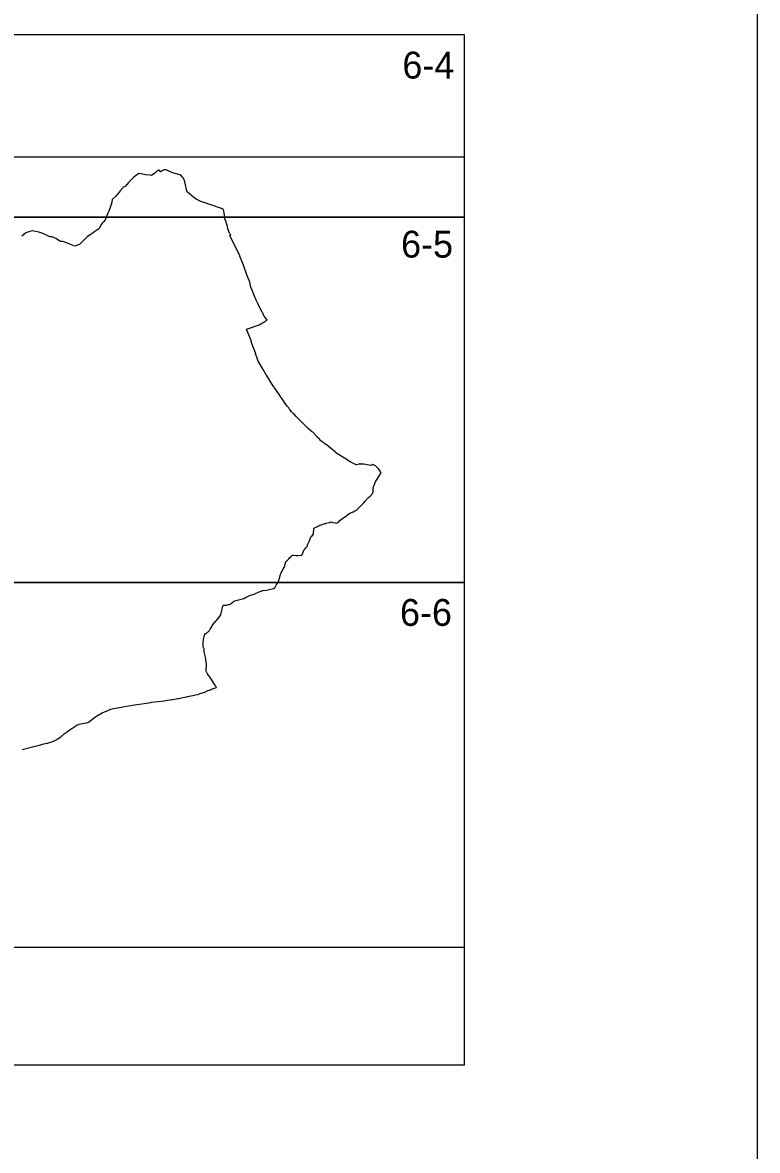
# Model space of a CAD drawing. Extents: x -447352 to -425530, y -1135906 to -1121091.
# Drawn here: x -444012.9 to -443761.4, y -1122276.2 to -1121890.1 of the extents above; entities that cross this region are included whole.
import ezdxf

# ---------------------------------------------------------------- set-up
doc = ezdxf.new("R2010")
doc.units = 0
for name, color, linetype in [('Vrstva 1', 7, 'Continuous'), ('Vrstva 10', 7, 'Continuous'), ('Vrstva 4', 7, 'Continuous')]:
    doc.layers.add(name, color=color, linetype=linetype)

msp = doc.modelspace()

# ---------------------------------------------------------------- linework, layer by layer
at = {"layer": 'Vrstva 1'}
msp.add_lwpolyline([(-445246.36, -1121535.97), (-445246.36, -1122585.97), (-443761.36, -1122585.97), (-443761.36, -1121535.97)], close=True, dxfattribs=at)
msp.add_lwpolyline([(-444013.07, -1122138.88), (-444009.53, -1122138.01), (-444006.76, -1122137.34), (-444006.09, -1122137.13), (-444004.6, -1122136.77), (-444004.39, -1122136.71), (-444002.96, -1122136.32), (-444002.36, -1122136.06), (-444002.14, -1122135.96), (-444001.98, -1122135.9), (-444001.16, -1122135.45), (-444001.1, -1122135.41), (-443999.79, -1122134.63), (-443998.64, -1122133.58), (-443997.99, -1122133.08), (-443997.86, -1122132.97), (-443997.84, -1122132.96), (-443997.68, -1122132.83), (-443997.53, -1122132.73), (-443996.73, -1122132.17), (-443996.67, -1122132.13), (-443996.6, -1122132.08), (-443996.09, -1122131.73), (-443995.72, -1122131.47), (-443995.06, -1122131.01), (-443994.47, -1122130.6), (-443994.31, -1122130.63), (-443994.3, -1122130.63), (-443994.28, -1122130.61), (-443993.55, -1122130.22), (-443990.59, -1122129.64), (-443990.17, -1122129.49), (-443988.14, -1122127.86), (-443987.67, -1122127.52), (-443987.64, -1122127.5), (-443987.28, -1122127.24), (-443987.1, -1122127.12), (-443985.71, -1122126.42), (-443984.3, -1122125.78), (-443984, -1122125.63), (-443982.74, -1122125.17), (-443981.74, -1122124.92), (-443976.03, -1122123.86), (-443974.61, -1122123.6), (-443972.9, -1122123.35), (-443969.03, -1122122.78), (-443968.79, -1122122.75), (-443964.49, -1122122.23), (-443963.96, -1122122.17), (-443961.81, -1122121.81), (-443961.49, -1122121.76), (-443959.83, -1122121.49), (-443959.43, -1122121.42), (-443958.02, -1122121.13), (-443956.73, -1122120.86), (-443956.52, -1122120.82), (-443955.35, -1122120.59), (-443954.68, -1122120.46), (-443954.66, -1122120.46), (-443953.75, -1122120.25), (-443953.68, -1122120.23), (-443953.03, -1122120.07), (-443952.68, -1122119.96), (-443951.79, -1122119.67), (-443951.35, -1122119.52), (-443950.7, -1122119.28), (-443950.58, -1122119.24), (-443949.49, -1122118.75), (-443949.49, -1122118.75), (-443949.37, -1122118.71), (-443948.72, -1122118.48), (-443948.63, -1122118.45), (-443948.2, -1122118.29), (-443946.54, -1122117.71), (-443946.56, -1122117.66), (-443946.67, -1122117.49), (-443946.83, -1122117.26), (-443947.05, -1122116.94), (-443948.75, -1122114.3), (-443948.96, -1122113.95), (-443949.13, -1122113.68), (-443949.57, -1122112.97), (-443950.1, -1122112.12), (-443949.94, -1122109.76), (-443949.93, -1122109.67), (-443950.32, -1122107.37), (-443950.32, -1122107.35), (-443950.33, -1122107.33), (-443950.33, -1122107.33), (-443950.33, -1122107.3), (-443950.74, -1122105.47), (-443950.75, -1122105.28), (-443950.81, -1122104.48), (-443950.91, -1122104.2), (-443950.92, -1122104.18), (-443951.03, -1122103.96), (-443951.07, -1122103.88), (-443951.08, -1122103.5), (-443951.11, -1122102.8), (-443951.06, -1122102.31), (-443951.06, -1122102.29), (-443950.97, -1122101.43), (-443950.95, -1122101.32), (-443950.66, -1122099.68), (-443950.58, -1122099.6), (-443950.28, -1122099.26), (-443950.22, -1122099.19), (-443949.96, -1122099.07), (-443949.9, -1122099.01), (-443949.64, -1122098.81), (-443949.41, -1122098.63), (-443949.2, -1122098.47), (-443949.14, -1122098.43), (-443949.06, -1122098.3), (-443948.98, -1122098.18), (-443948.87, -1122098.01), (-443948.65, -1122097.68), (-443948.23, -1122097.03), (-443948.1, -1122096.78), (-443948.09, -1122096.77), (-443947.95, -1122096.48), (-443947.9, -1122096.39), (-443947.72, -1122096.06), (-443947.58, -1122095.91), (-443947.28, -1122095.6), (-443947.11, -1122095.42), (-443946.83, -1122095.07), (-443946.7, -1122094.9), (-443946.01, -1122094.05), (-443945.35, -1122093.24), (-443945.06, -1122092.88), (-443944.82, -1122091.71), (-443944.76, -1122091.48), (-443944.69, -1122091.2), (-443944.37, -1122089.89), (-443944.29, -1122089.61), (-443944.29, -1122089.58), (-443944.27, -1122089.53), (-443944.11, -1122089.52), (-443944.09, -1122089.52), (-443943.85, -1122089.52), (-443943.16, -1122089.5), (-443943.15, -1122089.5), (-443943.12, -1122089.5), (-443942.44, -1122089.32), (-443942.24, -1122089.26), (-443941.82, -1122089.15), (-443941.8, -1122089.14), (-443941.74, -1122089.08), (-443941.44, -1122088.8), (-443941.32, -1122088.72), (-443940.98, -1122088.46), (-443940.56, -1122088.14), (-443940.49, -1122088.12), (-443939.93, -1122087.96), (-443937.23, -1122087.2), (-443936.64, -1122086.93), (-443936.31, -1122086.77), (-443936.26, -1122086.75), (-443936.16, -1122086.7), (-443935.8, -1122086.52), (-443935.75, -1122086.5), (-443935.72, -1122086.48), (-443935.71, -1122086.48), (-443935.68, -1122086.46), (-443935.37, -1122086.31), (-443935.31, -1122086.27), (-443935.2, -1122086.22), (-443934.12, -1122085.89), (-443933.69, -1122085.71), (-443933.17, -1122085.49), (-443932.16, -1122085.08), (-443930.74, -1122084.45), (-443930.6, -1122084.44), (-443929.47, -1122084.39), (-443927.07, -1122083.83), (-443926.54, -1122083.43), (-443926.47, -1122083.31), (-443926.38, -1122083.13), (-443926.12, -1122082.62), (-443925.77, -1122082.19), (-443925.75, -1122082.16), (-443925.54, -1122081.87), (-443925.43, -1122081.71), (-443925.42, -1122081.7), (-443924.88, -1122079.92), (-443924.87, -1122079.89), (-443924.67, -1122078.94), (-443924.41, -1122078.48), (-443924.22, -1122078.15), (-443923.67, -1122077.03), (-443923.29, -1122076.52), (-443923.26, -1122076.39), (-443923.19, -1122076.09), (-443923.16, -1122075.95), (-443923.1, -1122075.7), (-443923.08, -1122075.6), (-443922.76, -1122074.59), (-443922.75, -1122074.58), (-443922.46, -1122074.3), (-443921.8, -1122073.67), (-443921.75, -1122073.62), (-443921.28, -1122073.14), (-443921.02, -1122072.88), (-443920.92, -1122072.77), (-443920.55, -1122072.45), (-443920.51, -1122072.45), (-443920.5, -1122072.45), (-443920.09, -1122072.44), (-443919.92, -1122072.45), (-443919.29, -1122072.47), (-443918.58, -1122072.47), (-443917.61, -1122072.38), (-443917.58, -1122072.38), (-443917.33, -1122072.35), (-443917.11, -1122071.99), (-443917.06, -1122071.86), (-443917.04, -1122071.81), (-443917.02, -1122071.75), (-443916.66, -1122070.73), (-443916.52, -1122070.56), (-443916.42, -1122070.45), (-443916.38, -1122070.41), (-443916.32, -1122070.33), (-443916.2, -1122070.2), (-443915.93, -1122069.88), (-443915.84, -1122069.78), (-443915.74, -1122069.66), (-443915.4, -1122069.27), (-443915.33, -1122068.88), (-443915.27, -1122068.57), (-443915.2, -1122068.44), (-443914.65, -1122067.52), (-443914.54, -1122067.13), (-443914.35, -1122066.43), (-443914.23, -1122066.14), (-443913.94, -1122065.87), (-443913.39, -1122065.36), (-443913.32, -1122065.3), (-443913.22, -1122063.19), (-443912.2, -1122062.7), (-443911.8, -1122062.49), (-443911.55, -1122062.36), (-443911.26, -1122062.2), (-443911.04, -1122062.12), (-443910.7, -1122061.99), (-443910.65, -1122061.98), (-443909.56, -1122061.57), (-443909.55, -1122061.57), (-443909.06, -1122061.51), (-443908.98, -1122061.49), (-443907.95, -1122061.23), (-443907.8, -1122061.19), (-443907.71, -1122061.16), (-443907.54, -1122061.11), (-443907.01, -1122060.94), (-443907.01, -1122060.94), (-443907, -1122060.95), (-443907, -1122060.95), (-443906.97, -1122061.01), (-443906.84, -1122061.23), (-443905.96, -1122061.33), (-443905.76, -1122061.35), (-443905.4, -1122061.39), (-443905.31, -1122061.35), (-443904.88, -1122061.17), (-443904.23, -1122060.46), (-443902.59, -1122059.3), (-443902.5, -1122059.23), (-443902.33, -1122059.12), (-443901.82, -1122058.7), (-443901.07, -1122058.1), (-443899.8, -1122057.53), (-443899.18, -1122057.26), (-443898.64, -1122057.02), (-443898.58, -1122056.99), (-443896.93, -1122055.32), (-443896.09, -1122054.43), (-443895.73, -1122054.05), (-443894.54, -1122052.69), (-443893.94, -1122052.23), (-443893.89, -1122052.19), (-443893.05, -1122051.18), (-443892.85, -1122050.61), (-443892.94, -1122049.28), (-443892.72, -1122048.79), (-443892.08, -1122047.34), (-443890.62, -1122044.86), (-443890.59, -1122044.81), (-443890.59, -1122044.81), (-443890.57, -1122044.78), (-443890.54, -1122044.74), (-443890.39, -1122044.55), (-443890.13, -1122044.21), (-443890.39, -1122043.91), (-443890.53, -1122043.69), (-443891, -1122042.95), (-443891.2, -1122042.76), (-443891.35, -1122042.6), (-443891.54, -1122042.4), (-443892.12, -1122041.83), (-443892.97, -1122041.36), (-443893.42, -1122041.54), (-443893.75, -1122041.66), (-443895.5, -1122041.39), (-443896.11, -1122041.3), (-443896.25, -1122041.29), (-443896.84, -1122041.27), (-443897.22, -1122041.22), (-443897.38, -1122041.19), (-443897.42, -1122041.19), (-443897.45, -1122041.18), (-443897.45, -1122041.18), (-443897.48, -1122041.19), (-443897.58, -1122041.22), (-443897.71, -1122041.25), (-443898.61, -1122041.49), (-443898.68, -1122041.46), (-443900.75, -1122040.42), (-443902.77, -1122039.14), (-443905.68, -1122037.32), (-443905.84, -1122037.18), (-443905.88, -1122037.15), (-443905.97, -1122037.07), (-443907.11, -1122036.14), (-443908.26, -1122035.09), (-443908.37, -1122034.99), (-443909.58, -1122034.23), (-443909.86, -1122034), (-443910.49, -1122033.5), (-443910.8, -1122033.26), (-443911.3, -1122032.73), (-443912.02, -1122031.97), (-443912.17, -1122031.81), (-443912.63, -1122031.32), (-443913.6, -1122030.29), (-443913.8, -1122030.18), (-443913.8, -1122030.18), (-443913.98, -1122030.09), (-443914.18, -1122029.99), (-443915.01, -1122029.16), (-443915.64, -1122028.53), (-443916.82, -1122027.36), (-443917.75, -1122026.42), (-443917.91, -1122026.27), (-443918.35, -1122025.82), (-443918.59, -1122025.58), (-443918.68, -1122025.49), (-443918.72, -1122025.45), (-443919.24, -1122024.93), (-443919.88, -1122024.28), (-443919.96, -1122024.2), (-443919.98, -1122024.18), (-443920.13, -1122024.03), (-443920.96, -1122023.19), (-443921.34, -1122022.69), (-443921.62, -1122022.32), (-443921.94, -1122021.89), (-443922.3, -1122021.41), (-443923.25, -1122020.15), (-443923.62, -1122019.61), (-443926.16, -1122015.87), (-443926.33, -1122015.61), (-443927.1, -1122014.42), (-443927.77, -1122013.41), (-443928.61, -1122012.08), (-443929.41, -1122010.81), (-443929.49, -1122010.68), (-443930.58, -1122008.83), (-443932.26, -1122005.98), (-443932.26, -1122005.97), (-443932.26, -1122005.97), (-443932.27, -1122005.97), (-443932.6, -1122004.99), (-443933.05, -1122003.69), (-443933.11, -1122003.49), (-443934.49, -1121999.98), (-443934.78, -1121998.73), (-443936.26, -1121995.05), (-443935.63, -1121994.85), (-443931.91, -1121993.61), (-443929.94, -1121992.39), (-443929.76, -1121992.28), (-443929.7, -1121992.24), (-443929.5, -1121992.12), (-443929.23, -1121991.95), (-443930.15, -1121990.76), (-443931.56, -1121987.98), (-443932.31, -1121986.51), (-443932.84, -1121985.35), (-443932.86, -1121985.31), (-443932.92, -1121985.18), (-443932.93, -1121985.15), (-443932.95, -1121985.12), (-443932.99, -1121985.03), (-443933.32, -1121984.3), (-443933.64, -1121983.51), (-443934.35, -1121981.74), (-443934.76, -1121980.7), (-443934.91, -1121980.07), (-443935.17, -1121978.94), (-443935.91, -1121977.05), (-443936.11, -1121976.45), (-443937.05, -1121973.82), (-443937.32, -1121973.1), (-443938.51, -1121970.01), (-443938.58, -1121969.83), (-443938.61, -1121969.75), (-443941.96, -1121962.94), (-443941.65, -1121962.8), (-443941.63, -1121962.79), (-443941.73, -1121962.62), (-443941.81, -1121962.52), (-443941.98, -1121962.29), (-443942.04, -1121962.21), (-443942.65, -1121960.73), (-443942.7, -1121960.44), (-443942.8, -1121959.98), (-443942.81, -1121959.92), (-443943.32, -1121958.08), (-443943.62, -1121957.45), (-443943.63, -1121957.37), (-443943.67, -1121957.01), (-443943.81, -1121955.92), (-443944.09, -1121954.08), (-443944.15, -1121954.06), (-443944.45, -1121953.96), (-443944.83, -1121953.7), (-443944.84, -1121953.7), (-443949.14, -1121952.29), (-443951.93, -1121951.31), (-443953.24, -1121950.69), (-443954.21, -1121950.13), (-443954.93, -1121949.35), (-443956.61, -1121948.08), (-443956.67, -1121947.78), (-443957.25, -1121945.08), (-443957.4, -1121944.54), (-443957.58, -1121944.03), (-443957.63, -1121943.87), (-443957.88, -1121943.35), (-443958.13, -1121943.04), (-443958.71, -1121942.35), (-443959.46, -1121942.14), (-443961.64, -1121941.48), (-443963.73, -1121940.52), (-443964.35, -1121940.52), (-443965.3, -1121940.89), (-443965.43, -1121940.98), (-443965.5, -1121941.03), (-443965.64, -1121941.13), (-443965.68, -1121941.16), (-443965.7, -1121941.14), (-443965.91, -1121940.89), (-443966.16, -1121940.61), (-443966.24, -1121940.51), (-443966.33, -1121940.55), (-443966.84, -1121940.94), (-443967.03, -1121941.09), (-443967.7, -1121941.61), (-443968.45, -1121942.17), (-443968.79, -1121942.39), (-443969.38, -1121942.35), (-443970.86, -1121942.2), (-443971.32, -1121942.11), (-443972.91, -1121941.79), (-443973.21, -1121941.9), (-443973.77, -1121942.25), (-443974.32, -1121942.57), (-443974.81, -1121943.03), (-443975.34, -1121943.52), (-443975.74, -1121943.91), (-443975.75, -1121943.92), (-443976.08, -1121944.26), (-443976.21, -1121944.4), (-443976.72, -1121944.95), (-443977.17, -1121945.5), (-443977.33, -1121945.69), (-443977.69, -1121946.12), (-443978.43, -1121946.45), (-443978.45, -1121946.45), (-443978.65, -1121946.7), (-443979.51, -1121947.72), (-443979.89, -1121948.17), (-443981.02, -1121949.53), (-443981.03, -1121949.54), (-443982.27, -1121950.71), (-443982.39, -1121951.55), (-443982.44, -1121951.92), (-443982.48, -1121952.02), (-443982.96, -1121953.37), (-443983.4, -1121954.61), (-443983.43, -1121954.69), (-443983.73, -1121955.38), (-443984.66, -1121957.56), (-443984.68, -1121957.57), (-443985.25, -1121958.25), (-443985.55, -1121958.6), (-443985.55, -1121958.61), (-443985.89, -1121959.15), (-443986.76, -1121960.54), (-443986.85, -1121960.68), (-443987.02, -1121960.81), (-443987.55, -1121961.2), (-443988.16, -1121961.65), (-443988.16, -1121961.65), (-443989.13, -1121962.28), (-443989.26, -1121962.37), (-443989.44, -1121962.49), (-443990.74, -1121963.35), (-443990.75, -1121963.36), (-443991.01, -1121963.62), (-443991.13, -1121963.74), (-443991.35, -1121963.97), (-443991.63, -1121964.25), (-443992.2, -1121964.82), (-443993.36, -1121965.98), (-443993.56, -1121966.06), (-443995.06, -1121966.63), (-443997.87, -1121965.51), (-443997.87, -1121965.52), (-443997.88, -1121965.54), (-443998.79, -1121965.16), (-443999.1, -1121965.03), (-443999.12, -1121965.03), (-443999.51, -1121965.03), (-443999.99, -1121965.03), (-444001.55, -1121964.04), (-444001.81, -1121963.91), (-444002.1, -1121963.75), (-444002.16, -1121963.72), (-444002.2, -1121963.7), (-444002.74, -1121963.47), (-444002.79, -1121963.47), (-444002.8, -1121963.47), (-444002.95, -1121963.46), (-444003.07, -1121963.45), (-444003.38, -1121963.43), (-444003.4, -1121963.43), (-444003.4, -1121963.43), (-444003.51, -1121963.39), (-444003.75, -1121963.29), (-444004.35, -1121963.04), (-444004.51, -1121962.97), (-444006.03, -1121962.24), (-444006.65, -1121962.06), (-444007.32, -1121961.86), (-444009.64, -1121961.43), (-444009.65, -1121961.43), (-444010.05, -1121961.54), (-444011.79, -1121962.12), (-444011.92, -1121962.23), (-444013.13, -1121963.19)], dxfattribs=at)
at = {"layer": 'Vrstva 10'}
msp.add_lwpolyline([(-443861.77, -1121936.02), (-443861.77, -1122247), (-444194.64, -1122247), (-444194.64, -1122081.7), (-444174.27, -1122081.7), (-444174.27, -1121956.7), (-444174.27, -1121936.02), (-443861.77, -1121936.02)], dxfattribs=at)
at = {"layer": 'Vrstva 4'}
msp.add_line((-444174.27, -1121894.2), (-443861.77, -1121894.2), dxfattribs=at)
msp.add_lwpolyline([(-443861.77, -1121894.2), (-443861.77, -1121956.7), (-444018.02, -1121956.7), (-444018.02, -1121894.2)], dxfattribs=at)
for points in [[(-443861.77, -1121956.7), (-443861.77, -1122081.7), (-444018.02, -1122081.7), (-444018.02, -1121956.7)], [(-443861.77, -1122081.7), (-443861.77, -1122206.7), (-444018.02, -1122206.7), (-444018.02, -1122081.7)]]:
    msp.add_lwpolyline(points, close=True, dxfattribs=at)

# ---------------------------------------------------------------- texts
at = {"layer": 'Vrstva 1'}
for s, p in [('6-4', (-443882.9, -1121909.25)), ('6-5', (-443883.35, -1121970.54)), ('6-6', (-443883.72, -1122096.61))]:
    msp.add_text(s, height=9.2, dxfattribs=at).set_placement(p)

doc.saveas('drawing.dxf')
